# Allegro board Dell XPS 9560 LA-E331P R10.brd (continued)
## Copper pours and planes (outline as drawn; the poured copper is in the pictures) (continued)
LX_1.8V on TOP (solid shape): 247.91,105.29 247.91,103.26 247.71,103.07 245.87,103.07 245.37,103.58 245.37,104.72 246.13,105.48 247.71,105.48
LX_1.8V on BOTTOM (solid shape): 246.31,105.39 246.31,104.72 246.55,104.48 246.86,104.48 247.14,104.76 247.14,105.26 247.24,105.35 248,105.35 248.1,105.25 248.1,103.96 247.78,103.64 247.02,103.64 246.51,103.13 245.81,103.13 245.43,103.51 245.43,103.89 245.43,103.98 246.05,104.6 246.05,104.71 246.05,104.71 246.05,105.4 246.11,105.47 246.23,105.47
LX_1V on BOTTOM (solid shape): 127.76,9.09 127.76,7.82 128.52,7.06 130.49,7.06 130.88,6.67 132.07,6.67 132.07,5.47 130.99,5.47 130.84,5.32 130.84,4.35 129.92,3.44 129.92,2.23 129.67,1.98 127.45,1.98 127.16,2.26 127.16,6.14 126.15,7.14 126.15,9.18 126.31,9.34 127.51,9.34
LX_1VSP on TOP (solid shape): 234.38,115.71 234.38,114.31 234,113.93 232.09,113.93 231.84,114.18 231.84,115.77 231.97,115.9 234.19,115.9
LX_1VSP on TOP (solid shape): 239.84,116.02 239.84,115.2 238.91,114.27 238.87,114.26 238.82,114.25 237.87,114.25 237.75,114.37 237.75,114.82 239.05,116.12 239.75,116.12
LX_1VSP on BOTTOM (solid shape): 238.25,115.45 239.59,115.45 239.71,115.32 239.71,114.44 239.65,114.37 238.44,114.37 238,113.93 238,113.29 237.43,112.72 234.32,112.72 233.87,113.17 233.87,116.02 234.13,116.28 234.32,116.28 234.38,116.34 237.36,116.34
LX_3V on TOP (solid shape): 344.62,23.63 344.62,22.74 344.49,22.61 344.49,21.66 344.3,21.66 344.3,22.55 344.04,22.81 344.04,23.5 344.12,23.58 344.12,23.67 344.21,23.76 344.49,23.76
LX_3V on TOP (solid shape): 339.31,31.62 339.31,25.54 340.24,24.62 340.24,23.63 340.08,23.47 338.17,23.47 336.93,22.23 336.93,19 336.74,18.8 334.27,18.8 333.95,19.12 333.95,20.52 333.63,20.84 331.03,20.84 330.9,20.96 330.9,22.17 331.22,22.49 333.5,22.49 334.33,23.31 334.33,27.5 334.65,27.82 336.49,27.82 336.86,28.2 336.86,30.07 336.68,30.25 336.68,31.98 336.75,32.04 338.89,32.04
LX_3V on IN6 (solid shape): 339.6,28.67 339.6,27.26 341.45,25.41 343.07,25.41 344.73,23.76 344.73,22.74 344.46,22.48 343.72,22.48 342.38,23.81 340.25,23.81 337.82,26.24 337.82,28.67 338.16,29.01 339.26,29.01
LX_5V on TOP (solid shape): 344.49,19.19 344.49,18.3 345.06,17.73 346.77,17.73 347.28,17.22 347.28,16.71 347.16,16.58 345.12,16.58 344.74,16.96 344.74,17.66 344.62,17.79 344.43,17.79 344.3,17.92 344.3,19.19 344.36,19.25 344.43,19.25
LX_5V on TOP (solid shape): 337.69,14.3 337.69,12.14 338.14,11.69 340.11,11.69 340.42,11.38 340.42,10.17 340.11,9.85 338.33,9.85 338.01,9.53 338.01,4.01 337.82,3.82 333.19,3.82 332.87,4.14 332.87,7.82 332.3,8.39 327.47,8.39 326.58,9.28 326.58,11.21 330.23,11.21 330.23,10.08 330.5,9.82 331.68,9.82 331.95,10.08 331.95,11.21 331.75,11.41 330.43,11.41 330.23,11.21 326.58,11.21 326.58,11.38 326.96,11.76 331.03,11.76 332.3,13.03 332.3,14.11 332.74,14.55 337.44,14.55
LX_5V on IN1 (solid shape): 338.77,8.71 338.27,8.2 337.88,8.2 337.38,8.71 336.68,8.71 336.36,9.03 336.36,9.47 336.55,9.66 337.82,9.66
LX_5V on IN1 (solid shape): 348.81,16.9 348.81,16.33 348.5,16.02 348.37,16.02 348.27,15.92 347.45,16.74 346.93,16.74 346.4,17.27 346.4,17.59 346.57,17.76 346.58,17.76 346.74,17.92 347.79,17.92
Net_853 on BOTTOM (solid shape): 241.69,29.93 226.69,29.93 226.69,39.93 241.69,39.93
Net_854 on BOTTOM (solid shape): 210.38,30.43 202.38,30.43 202.38,38.43 210.38,38.43
Net_854 on BOTTOM (solid shape): 222.19,30.3 214.19,30.3 214.19,38.3 222.19,38.3
PBAT_PRES# on TOP (solid shape): 28.87,12.86 28.87,10.47 28.63,10.23 27,10.23 26.58,10.65 26.58,13.44 26.32,13.69 25.4,13.69 25.22,13.88 25.22,14.87 25.35,14.99 26.74,14.99
PP_HV on TOP (solid shape): 25.01,56.13 25.01,55.18 24.66,54.83 23.76,54.83 23.64,54.95 23.64,56 23.54,56.1 23.54,56.97 23.58,57.01 24.12,57.01
PP_HV on BOTTOM (solid shape): 24.05,56.98 24.05,56.79 24.2,56.64 24.36,56.64 24.58,56.42 24.58,56.19 24.58,55.3 24.38,55.1 24.38,54.43 24.07,54.11 24.07,53.45 23.92,53.3 22.97,53.3 22.92,53.35 22.92,54.24 23.59,54.91 23.59,56.01 23.29,56.31 23.29,56.53 23.46,56.7 23.53,56.7 23.7,56.88 23.7,56.95 23.78,57.03 24,57.03
PSID on BOTTOM (solid shape): 19.77,79.22 19.77,72.18 19.63,72.04 19.63,71.99 19.6,71.87 19.6,71.75 19.44,71.58 19.17,71.58 18.92,71.83 18.92,79.22 18.96,79.26 19.74,79.26
RING2 on TOP (solid shape): 12.3,58.78 12.33,58.74 12.37,58.7 12.38,58.68 12.38,58.37 12.61,58.14 13.44,58.14 13.61,57.97 13.61,57.18 13.56,57.13 12.05,57.13 11.74,57.45 11.74,58.63 11.89,58.78
RING2 on BOTTOM (solid shape): 8.9,44.45 8.9,43.37 8.98,43.28 8.98,41.5 8.88,41.41 8.77,41.41 8.71,41.46 8.71,42.5 8.67,42.54 8.67,43.19 8.65,43.2 8.65,43.23 8.42,43.46 8.42,43.88 8.37,43.93 8.37,44.41 8.51,44.55 8.8,44.55
RING2 on IN1 (solid shape): 14.49,57.6 14.49,56.9 14.28,56.69 13.49,56.69 12.99,57.18 12.13,57.18 11.76,57.55 11.76,58.09 11.96,58.29 13.81,58.29
RING2 on IN1 (solid shape): 9.31,45.82 9.31,44.78 9.05,44.52 9.02,44.49 8.99,44.46 8.92,44.24 8.99,44.02 8.99,43.88 8.92,43.69 8.96,43.49 8.76,43.3 8.37,43.3 8.19,43.48 8.19,43.94 8.23,44.1 8.19,44.27 8.13,44.36 8.04,44.42 7.91,44.55 7.91,45.32 7.92,45.33 7.92,45.53 8.29,45.91 9.22,45.91
RING2_L on TOP (solid shape): 11.56,58.88 11.56,58.2 11.11,57.75 7.19,57.75 6.91,57.46 5.71,57.46 5.06,58.11 4.38,58.11 4.35,58.08 4.35,57.92 4.63,57.64 4.63,56.74 3.75,55.86 2.5,55.86 2.35,56.02 2.35,56.68 2.55,56.88 2.94,56.88 3.63,57.57 3.63,58.57 3.73,58.67 4.35,58.67 4.35,58.67 4.48,58.81 4.5,58.82 5.46,58.82 5.77,58.52 5.77,58.51 5.99,58.29 6.31,58.29 6.34,58.33 6.35,58.33 6.96,58.94 11.5,58.94
SD_REG2 on BOTTOM (solid shape): 343.69,39.9 343.69,39.43 343.39,39.13 342.81,39.13 342.81,39.12 341.85,39.12 341.42,38.69 341.34,38.69 341.28,38.75 341.28,39.54 341.62,39.88 342.84,39.88 342.98,40.01 343.57,40.01
SLEEVE on TOP (solid shape): 15.11,57.76 15.11,56.46 15.11,56.46 15.11,56.24 14.88,56.01 14.41,56.01 14.3,56.11 14.3,56.38 13.75,56.93 13.75,57.89 13.85,57.98 14.89,57.98
SLEEVE on TOP (solid shape): 9.53,45.18 9.53,43.59 9.41,43.48 9.12,43.48 9.01,43.59 9.01,44.44 8.86,44.58 8.75,44.58 8.74,44.59 8.64,44.6 8.54,44.59 8.53,44.58 6.87,44.58 6.74,44.71 6.74,45.32 6.83,45.4 9.31,45.4
SLEEVE on BOTTOM (solid shape): 9.54,44.32 9.54,44.06 9.54,44.06 9.54,43.66 9.55,43.65 9.55,43.49 9.36,43.3 9.36,41.49 9.28,41.42 9.18,41.42 9.12,41.48 9.12,43.32 9.02,43.42 9.02,44.3 9.1,44.38 9.48,44.38
SLEEVE on IN2 (solid shape): 15.1,57.09 15.1,55.36 14.99,55.25 14.19,55.25 13.98,55.45 13.98,57.02 14.16,57.2 14.99,57.2
SLEEVE on IN2 (solid shape): 10.19,45.6 10.19,44.64 10.13,44.58 10,44.58 9.92,44.59 9.84,44.58 9.77,44.58 9.71,44.52 9.56,44.23 9.71,43.94 9.71,43.68 9.41,43.38 9.04,43.38 8.94,43.47 8.96,43.51 8.99,43.69 8.93,43.87 8.92,43.88 8.92,43.98 8.94,44 8.94,44.05 8.95,44.06 8.96,44.39 8.7,44.59 8.66,44.6 8.66,45.49 8.9,45.74 10.05,45.74
SLEEVE_L on TOP (solid shape): 3.71,45.77 3.71,45.57 4.02,45.27 4.73,45.27 5.16,45.69 6.29,45.69 6.41,45.57 6.41,44.76 6.35,44.7 3.07,44.7 2.66,45.11 2.66,45.72 2.74,45.8 3.68,45.8
SNB_0.95V on BOTTOM (solid shape): 112.14,58.62 112.14,57.03 112.02,56.9 111,56.9 110.81,57.1 110.81,57.86 110.55,58.11 109.54,58.11 109.48,58.17 109.48,58.68 109.6,58.81 111.95,58.81
SNB_1V on BOTTOM (solid shape): 130.94,9.19 130.94,8.39 130.87,8.32 130.22,8.32 130.03,8.14 130.03,7.58 129.83,7.37 128.84,7.37 128.72,7.5 128.72,9.09 128.91,9.28 130.84,9.28
SNB_1VSP on TOP (solid shape): 235.97,115.83 235.97,115.39 236.22,115.13 237.36,115.13 237.49,115.01 237.49,114.18 237.36,114.05 234.95,114.05 234.76,114.25 234.76,115.9 234.82,115.96 235.84,115.96
SNUB_1.2V on BOTTOM (solid shape): 267.46,27.76 267.46,26.11 267.27,25.92 266.32,25.92 266.19,26.04 266.19,26.74 265.94,27 265.05,27 264.86,27.19 264.86,27.76 265.05,27.95 267.27,27.95
SNUB_3V on TOP (solid shape): 335.18,31.88 335.18,29.95 334.96,29.73 332.78,29.73 332.67,29.83 332.67,30.48 332.81,30.62 333.66,30.62 334.03,30.99 334.03,31.99 334.07,32.03 335.04,32.03
SNUB_5V on TOP (solid shape): 340.3,14.74 340.3,12.9 340.17,12.77 338.46,12.77 338.27,12.96 338.27,14.87 338.46,15.06 339.98,15.06
SW_1.2V on BOTTOM (solid shape): 287.29,28.88 287.29,28.79 287.15,28.65 286.77,28.65 284.93,26.81 284.29,26.81 284.16,26.93 284.16,27.82 284.23,27.89 285.18,27.89 286.24,28.95 287.22,28.95
SW_1.2V on BOTTOM (solid shape): 269.8,33.51 269.8,32.85 270.22,32.43 271.37,32.43 271.53,32.27 271.53,30.3 271.78,30.04 272.37,30.04 272.95,29.47 272.95,25.87 272.86,25.79 268.86,25.79 268.54,26.11 268.54,27.82 266.96,29.41 266.96,33.44 267.14,33.63 269.68,33.63
SW_1.2V on IN6 (solid shape): 272.86,29.39 272.86,28 272.6,27.73 270.82,27.73 270.61,27.94 270.61,29.74 270.75,29.88 272.37,29.88
SW_1.2V on IN6 (solid shape): 286.45,28.45 286.45,28.11 285.59,27.25 283.5,27.25 283.4,27.36 283.4,28.22 283.54,28.36 284.56,28.36 284.77,28.16 285.46,28.16 285.93,28.63 286.28,28.63
SW_+1.35VRUN on TOP (solid shape): 198.31,117.29 198.31,116.59 198.44,116.47 199.91,116.47 200.2,116.18 200.2,111.76 199.98,111.54 199.01,111.54 198.9,111.64 198.9,113.47 198.69,113.67 197.74,113.67 197.55,113.86 197.55,114.44 197.36,114.63 197.36,117.29 197.49,117.42 198.18,117.42
SW_+1.35VRUN on BOTTOM (solid shape): 200.79,117.93 200.79,111.58 200.34,111.13 196.49,111.13 196.15,111.36 195.82,111.13 194.95,111.13 194.69,111.39 194.69,113.99 194.77,114.07 196.41,114.07 196.59,114.25 196.77,114.39 196.79,114.61 196.79,117.29 197.55,118.06 200.66,118.06
TBT_SVR_IND on BOTTOM (solid shape): 24.25,49.89 24.01,49.65 24.01,47.65 23.35,46.99 23.35,46.82 23.34,46.81 23.32,46.69 23.34,46.58 23.35,46.56 23.35,46.08 23.44,46 23.44,45.57 23.37,45.51 23.24,45.51 23.11,45.37 23.11,45.22 23.03,45.14 22.82,45.14 22.72,45.25 22.72,46.28 22.86,46.42 22.86,46.53 22.86,47.33 22.44,47.75 22.44,50.25 22.51,50.45 22.45,50.65 22.44,50.66 22.44,50.77 22.76,51.09 24.25,51.09
TBTA_VBUS_L on BOTTOM (solid shape): 28.54,62.97 28.54,61.85 28.88,61.51 28.88,60.6 28.76,60.47 28.11,60.47 27.76,60.13 27.34,60.13 27.13,60.16 26.96,60.03 26.87,59.94 26.73,59.94 26.7,59.91 26.35,59.91 26.25,59.82 25.68,59.82 25.61,59.84 25.58,59.9 25.51,60.05 25.36,60.11 25.29,60.11 25.2,60.19 25.2,60.48 25.2,60.53 25.34,60.66 25.42,60.66 25.43,60.67 25.47,60.67 25.6,60.8 25.6,60.9 25.61,60.9 25.61,61.07 25.7,61.16 26.32,61.16 26.42,61.26 26.44,61.26 26.68,61.46 26.62,61.77 26.62,62.05 26.63,62.06 26.66,62.2 26.63,62.34 26.63,62.35 26.63,62.77 26.99,63.13 28.39,63.13
TPM_VDD on TOP (solid shape): 158.87,11.98 158.87,11.85 158.86,11.85 158.86,11.23 158.52,10.89 158.52,8.91 158.37,8.76 156.31,8.76 156.25,8.82 156.25,9.02 156.33,9.1 157.5,9.1 157.63,9.23 157.63,9.76 157.4,9.99 157.4,11.99 157.5,12.09 158.76,12.09
UG_3V on TOP (solid shape): 330.69,22.61 330.69,20.92 330.6,20.84 330.07,20.84 329.88,21.03 329.88,22.61 330.01,22.74 330.55,22.74
UG_3V on TOP (solid shape): 343.7,22.26 343.7,21.33 343.66,21.29 343.55,21.29 343.45,21.39 343.45,22.01 343.35,22.11 343.09,22.11 342.46,22.74 342.46,22.93 342.58,23.06 342.9,23.06
UG_3V on IN1 (solid shape): 331.92,22.55 331.92,21.6 331.79,21.47 329.88,21.47 329.82,21.54 329.82,22.74 330.01,22.93 331.53,22.93
UG_3V on IN1 (solid shape): 343.47,23.25 343.47,22.23 343.35,22.11 342.77,22.11 341.76,23.12 341.76,23.44 342.33,24.01 342.71,24.01
UG_5V on TOP (solid shape): 331.82,11.15 331.82,10.14 331.63,9.95 330.55,9.95 330.36,10.14 330.36,11.15 330.49,11.28 331.69,11.28
UG_5V on TOP (solid shape): 343.71,19.28 343.71,18.37 343.63,18.3 342.33,18.3 342.27,18.36 342.27,18.68 342.46,18.87 343.41,18.87 343.47,18.93 343.47,19 343.47,19 343.47,19.25 343.53,19.31 343.68,19.31
UG_5V on IN1 (solid shape): 333.63,11.18 333.44,10.99 333.19,10.99 332.11,9.91 331.66,9.91 331.47,10.11 331.47,11.25 332.11,11.88 333.63,11.88
UG_5V on IN1 (solid shape): 344.3,17.92 344.3,17.15 343.98,16.84 343.73,16.84 342.71,17.85 342.52,17.85 342.2,18.17 342.2,18.61 342.39,18.8 343.41,18.8
VCORE_B+ on TOP (solid shape): 143.32,106.82 143.32,105.86 142.88,105.42 142.11,105.42 141.86,105.67 141.65,105.67 141.54,105.78 141.25,106.07 141.25,106.95 141.33,107.03 143.11,107.03
VCORE_B+ on TOP (solid shape): 140.14,113.42 140.14,112.44 140.91,111.68 140.91,108.25 140.69,108.03 139.11,108.03 138.78,108.36 138.78,113.08 138.84,113.2 138.84,113.32 139.05,113.53 140.03,113.53
VCORE_B+ on TOP (solid shape): 140.21,119.95 140.21,116.28 140.4,116.09 140.8,116.09 140.97,115.92 140.97,114.5 140.72,114.25 139.37,114.25 138.79,114.83 138.79,117.08 138.58,117.28 138.42,117.28 138.37,117.28 137.72,117.28 137.35,117.65 137.35,119.89 137.77,120.31 139.85,120.31
VCORE_B+ on TOP (solid shape): 162.4,118.39 162.4,117.94 162.18,117.72 162.18,117.17 161.99,116.98 161.23,116.98 160.97,116.72 159.8,116.72 159.15,116.08 159.15,115.62 159,115.46 156.08,115.46 155.95,115.59 155.95,117.42 156.18,117.65 156.84,117.65 157.24,118.06 158.34,118.06 158.35,118 158.36,117.95 158.38,117.9 158.41,117.85 158.44,117.81 158.48,117.78 158.52,117.75 158.57,117.72 158.62,117.71 158.67,117.7 158.73,117.7 158.78,117.71 158.83,117.72 158.88,117.75 158.92,117.78 158.96,117.81 159,117.85 159.02,117.9 159.04,117.95 159.05,118 159.06,118.06 159.05,118.11 159.04,118.16 159.02,118.21 159,118.26 158.96,118.3 158.92,118.33 158.88,118.36 158.83,118.39 158.78,118.4 158.73,118.41 158.67,118.41 158.62,118.4 158.57,118.39 158.52,118.36 158.48,118.33 158.44,118.3 158.41,118.26 158.38,118.21 158.36,118.16 158.35,118.11 158.34,118.06 157.24,118.06 157.88,118.69 162.09,118.69
VCORE_B+ on BOTTOM (solid shape): 162.43,118.25 162.43,117.99 162.13,117.69 162.13,117.11 162,116.98 161.48,116.98 161.27,116.76 161.26,116.76 160.64,116.13 159.62,116.13 159.04,115.55 159.04,115.41 159.02,115.39 156.09,115.39 156.02,115.46 156.02,115.83 155.93,115.92 155.39,115.92 155.3,116.01 155.3,116.12 155.32,116.15 155.89,116.15 156.03,116.28 156.03,116.91 156.06,116.94 158.62,116.94 159.26,117.57 159.26,118.09 159.51,118.35 159.59,118.35 159.59,118.39 162.29,118.39
VCORE_B+ on BOTTOM (solid shape): outline of 151 points within 126.48,103.86 143.43,119.39
VCORE_B+ on IN4 (solid shape): outline of 2312 points within 136.91,105.47 162.37,119.64
VCORE_B+ on IN6 (solid shape): 162.43,118.18 162.43,117.85 161.8,117.22 161.64,117.22 160.68,116.26 159.91,116.26 159.13,115.48 156.19,115.48 155.98,115.68 155.98,116.9 156.19,117.1 158.35,117.1 159.19,117.95 159.19,118.14 159.45,118.39 162.22,118.39
VCORE_B+ on IN6 (solid shape): 140.18,119.08 140.18,117.97 140.91,117.24 140.91,114.37 140.82,114.28 140.44,114.28 140.36,114.21 140.36,113.37 140.3,113.17 140.36,112.96 140.36,112.86 140.46,112.76 140.46,112.68 140.21,112.43 140.21,111.44 140.84,110.8 140.84,108.71 140.65,108.53 139.59,108.53 139.32,108.79 139.32,110.58 138.91,110.98 138.91,112.12 139.94,113.15 139.94,113.31 140.08,113.45 140.08,114.21 139.98,114.31 139.57,114.31 139.4,114.49 139.4,116.37 139.45,116.42 139.45,116.62 138.71,117.36 138.23,117.36 137.54,118.04 137.54,119.11 137.8,119.36 139.9,119.36
N09395 on BOTTOM (solid shape): 15.43,39.73 15.43,39.23 15.32,39.12 14.02,39.12 13.72,38.82 13.34,38.82 13.25,38.9 13.25,39.1 12.73,39.63 11.79,39.63 11.75,39.66 11.75,39.8 11.78,39.83 15.32,39.83
N09461 on TOP (solid shape): 13.52,38.07 13.52,37.55 13.45,37.47 13.02,37.47 12.89,37.35 12.89,36.79 12.65,36.55 12.65,36.18 12.55,36.08 12.09,36.08 12.09,36.66 12.39,36.97 12.39,37.64 12.46,37.71 12.46,38.18 12.53,38.25 13.34,38.25
N09461 on BOTTOM (solid shape): 13.66,37.99 13.66,37.57 13.54,37.44 13.17,37.44 12.99,37.63 11.76,37.63 11.71,37.67 11.71,37.78 11.76,37.83 12.74,37.83 12.99,38.07 13.58,38.07
N13272521 on TOP (solid shape): 108.84,61.48 108.84,60.46 108.65,60.27 106.81,60.27 106.68,60.4 106.68,61.03 106.74,61.1 107.63,61.1 108.08,61.54 108.78,61.54
N17034092 on TOP (solid shape): 341.2,22.23 341.2,21.57 341.22,21.57 341.65,21.14 342.04,21.14 342.34,20.84 343.35,20.84 343.41,20.78 343.41,20.64 343.37,20.6 342.31,20.6 342.21,20.7 342.07,20.7 342.07,20.7 341.12,20.7 341.08,20.66 340.35,20.66 340.3,20.7 340.3,22.26 340.39,22.35 341.08,22.35
N19473637 on TOP (solid shape): 182.31,17.43 182.31,16.89 184.09,15.11 184.09,14.19 183.82,13.93 182.65,13.93 182.13,13.41 180.95,13.41 180.87,13.48 180.87,14.55 180.46,14.97 180.46,16.42 180.82,16.79 180.82,17.76 180.89,17.83 181.92,17.83
N19912586 on TOP (solid shape): 177.61,107.13 177.61,104.72 177.27,104.38 176.57,104.38 176.34,104.61 176.34,107.13 176.47,107.26 177.48,107.26
N19912586 on BOTTOM (solid shape): 178.06,108.78 178.06,104.47 177.86,104.28 173.99,104.28 173.67,104.59 173.67,107.51 173.86,107.7 174.75,107.7 175.32,108.28 175.32,108.72 175.58,108.97 177.86,108.97
N22956922 on TOP (solid shape): outline of 1654 points within 193.5,68.02 202.9,91.45
N22956922 on BOTTOM (solid shape): outline of 528 points within 196.04,67.71 202.25,80.79
N22956922 on IN1 (solid shape): outline of 1947 points within 194.37,68.21 202.5,81.73
N48708347 on BOTTOM (solid shape): 283.53,29.09 283.53,26.87 283.47,26.81 282.77,26.81 282.7,26.87 282.7,29.03 282.83,29.16 283.47,29.16
N49571039 on TOP (solid shape): 134,8.06 134,6.8 133.16,5.95 132.66,5.45 131.34,5.45 131.19,5.6 131.19,6.49 131.97,7.27 132.24,7.27 133.17,8.2 133.86,8.2
N52699143 on TOP (solid shape): 33.47,4.45 33.47,1.6 33.4,1.53 31.75,1.53 31.66,1.63 31.66,4.39 31.78,4.52 33.4,4.52
N80922351 on TOP (solid shape): 249.05,110.94 249.05,109.8 248.79,109.55 246.51,109.55 246.44,109.61 246.44,110.86 246.71,111.13 248.86,111.13
N80922351 on BOTTOM (solid shape): 247.59,110.88 247.65,110.82 248.98,110.82 249.05,110.88 249.05,111.32 249.37,111.32 249.68,111.01 249.68,110.18 249.24,109.74 248.6,109.74 248.1,109.23 248.1,108.21 247.91,108.02 246.85,108.02 246.72,107.9 246.72,107.9 246.41,107.59 246.41,107.58 246.3,107.48 246.3,106.84 246.24,106.78 246.1,106.78 246.05,106.83 246.05,107.87 246.13,107.94 246.18,108.04 246.28,108.13 246.28,108.67 246.38,108.77 246.38,110.88 246.83,111.32 247.59,111.32
N80922387 on BOTTOM (solid shape): 249.46,106.38 249.46,104.38 249.34,104.26 248.72,104.26 248.54,104.45 248.54,106.41 248.65,106.53 249.31,106.53
N110703687 on TOP (solid shape): 175.96,100.91 175.96,99.83 175.26,99.13 175.26,97.86 174.94,97.54 173.8,97.54 173.67,97.67 173.67,99.39 173.93,99.64 174.5,99.64 175.07,100.21 175.07,101.04 175.13,101.1 175.77,101.1
N110833423 on TOP (solid shape): 177.93,99.51 177.93,97.86 176.98,96.91 175.79,96.91 175.58,97.13 175.58,99.26 176.02,99.7 177.74,99.7
N110833423 on BOTTOM (solid shape): 177.55,101.6 177.55,97.74 176.77,96.96 173.91,96.96 173.32,97.54 173.32,98.08 172.91,98.5 172.91,101.8 173.1,101.99 177.16,101.99
N111796536 on TOP (solid shape): 312.6,33.87 312.6,33.22 311.28,31.9 309.88,31.9 309.86,31.92 309.86,32.83 309.89,32.86 310.85,32.86 311.93,33.95 312.51,33.95
N111796622 on TOP (solid shape): 313.18,37.09 313.18,36.33 313.04,36.18 312.79,36.18 312.59,35.99 312.59,35.35 312.54,35.3 311.63,35.3 311.56,35.37 311.56,36.11 311.91,36.46 312.1,36.46 312.17,36.52 312.17,37.28 312.23,37.35 312.93,37.35
N116496514 on TOP (solid shape): 175.26,107.07 175.26,105.67 175.83,105.1 175.83,104.02 175.77,103.96 175.13,103.96 174.94,104.15 174.94,104.91 174.5,105.36 173.86,105.36 173.67,105.55 173.67,107.2 173.86,107.39 174.94,107.39
N119942216 on BOTTOM (solid shape): 27.69,79.19 27.69,77.1 27.12,76.53 26.93,76.53 26.54,76.15 26.54,75.57 26.42,75.45 24.65,75.45 24.33,75.13 24.33,72.31 24.2,72.17 20.62,72.17 20.55,72.18 20.49,72.18 20.46,72.18 20.4,72.24 20.4,79.13 20.53,79.26 27.62,79.26
N119944438 on TOP (solid shape): 53.35,16 53.45,16 53.51,15.95 53.51,15.39 52.16,14.04 51.37,14.04 51.18,13.85 51.18,13.34 51.06,13.22 50.8,13.22 50.67,13.34 50.67,13.98 50.74,14.04 50.74,15.34 50.86,15.47 52.29,15.47 52.64,15.82 52.64,15.95 52.71,16.01 53.34,16.01
N120361841 on TOP (solid shape): 57.77,3.03 58.71,3.03 58.77,2.97 58.77,2.44 58.68,2.35 57.1,2.35 56.97,2.47 56.55,2.47 56.43,2.6 56.43,3.26 56.48,3.31 57.49,3.31
N120533729 on TOP (solid shape): 276.93,9.19 276.93,8.86 276.4,8.86 276.4,8.43 276.93,8.43 276.93,7.94 277.16,7.71 277.7,7.71 277.95,7.46 277.95,6.53 277.86,6.44 275.75,6.44 275.63,6.56 275.63,7.32 275.29,7.65 274.49,7.65 274.19,7.95 274.19,8.88 274.58,9.27 276.84,9.27
N120553378 on TOP (solid shape): 309.37,23.63 309.37,21.03 309.25,20.9 307.4,20.9 307.08,21.23 307.08,21.7 307.61,21.7 307.61,22.13 307.07,22.13 307.07,22.82 306.58,23.31 306.58,24.01 306.71,24.14 308.87,24.14
N120970730 on TOP (solid shape): 150.05,101.74 150.05,100.66 149.42,100.02 147,100.02 146.75,100.28 146.75,101.06 146.97,101.28 147,101.28 147.65,101.93 149.86,101.93
N120971346 on BOTTOM (solid shape): 148.53,118.02 148.53,117.76 148.74,117.55 149.42,117.55 149.48,117.48 149.48,116.53 149.29,116.34 147.45,116.34 147.3,116.49 147.3,118.04 147.42,118.15 148.4,118.15
N120971480 on TOP (solid shape): 161.71,111.74 161.71,110.92 161.63,110.84 161.63,109.51 161.56,109.43 159.95,109.43 159.83,109.55 159.83,110.5 159.96,110.63 160.78,110.63 160.85,110.69 160.85,111.64 161.01,111.81 161.64,111.81
N120977227 on TOP (solid shape): 161.65,108.41 161.65,106.83 160.4,105.58 159.73,105.58 158.62,106.69 158.62,108.09 159.51,108.97 161.08,108.97
N120977227 on BOTTOM (solid shape): 158.57,112.98 158.57,112.65 159.27,111.95 161.11,111.95 161.32,111.74 161.32,106.29 160.91,105.88 160.86,105.88 160.71,105.72 159.36,105.72 158.95,106.14 158.93,106.17 158.93,107.17 158.65,107.45 156.02,107.45 155.7,107.77 155.7,112.47 156.05,112.81 156.05,113.04 156.11,113.1 158.44,113.1
N120977227 on IN6 (solid shape): 158.57,113.05 158.57,112.66 159.26,111.97 161.16,111.97 161.32,111.82 161.32,106.28 160.94,105.9 160.86,105.9 160.61,105.65 159.51,105.65 158.98,106.18 158.98,107.15 158.67,107.45 156.03,107.45 155.73,107.76 155.73,112.51 156.4,113.17 158.44,113.17
N120977691 on BOTTOM (solid shape): 146.56,117.93 146.56,116.44 146.56,116.37 147.24,115.68 149.25,115.68 149.4,115.53 149.4,113.78 149.05,113.42 147.96,113.42 147.73,113.19 147.73,112.82 147.71,112.81 147.71,110.85 147.64,110.78 145.2,110.78 144.97,111.01 144.97,113.93 144.21,114.69 143.31,114.69 143.25,114.75 143.25,116.73 143.36,116.85 144.16,116.85 144.46,117.15 144.46,117.99 144.53,118.06 146.43,118.06
N120977691 on IN6 (solid shape): 146.56,117.86 146.56,116.34 147.17,115.73 149.33,115.73 149.53,115.53 149.53,113.75 149.2,113.42 148.24,113.42 147.88,113.06 147.88,112.38 148.44,111.82 148.44,111.39 148.01,110.96 145.16,110.96 144.96,111.16 144.96,113.72 144.98,113.75 144.98,113.9 144.37,114.51 143.37,114.51 143.2,114.68 143.2,116.59 143.33,116.72 144.1,116.72 144.48,117.1 144.48,117.76 144.43,117.81 144.43,117.89 144.58,118.04 146.38,118.04
N121616264 on TOP (solid shape): 192.27,9.3 192.27,7.2 192.2,7.12 191.54,7.12 191.28,7.38 191.28,9.38 191.33,9.43 192.14,9.43
N121617759 on TOP (solid shape): 239.8,7.34 239.8,6.83 240.89,5.74 240.89,5.2 240.84,5.15 238.69,5.15 238.2,5.63 238.2,7.37 238.25,7.43 239.71,7.43
N121617766 on TOP (solid shape): 244.3,7.39 244.3,5.5 243.96,5.16 242.31,5.16 242.27,5.2 242.27,5.86 242.72,6.32 242.72,7.39 242.8,7.47 244.21,7.47
N121795600 on TOP (solid shape): 148.65,103.89 148.65,102.74 148.43,102.51 148.41,102.51 148.15,102.24 147.52,102.24 146.79,101.51 145.52,101.51 144.93,102.09 144.93,103.8 145.15,104.02 148.53,104.02
N121795600 on BOTTOM (solid shape): 144.75,110.47 148.51,110.47 148.97,110.02 148.97,106.1 148.82,105.95 147.86,105.95 147.73,105.83 147.73,104.57 147.83,104.47 148.65,104.47 148.97,104.15 148.97,101.96 148.6,101.59 146.71,101.59 146.6,101.48 145.75,101.48 144.97,102.26 144.97,107.76 143.74,108.99 143.22,108.99 143.19,109.02 143.19,111.03 143.23,111.07 144.15,111.07
N121795600 on IN6 (solid shape): 149.05,110.14 149.05,106.1 148.87,105.93 148.21,105.93 147.8,105.52 147.8,104.96 148.06,104.71 148.59,104.71 148.95,104.35 148.95,102.07 148.51,101.63 145.8,101.63 145.78,101.65 145.56,101.65 144.86,102.35 144.86,107.1 143.99,107.96 143.26,107.96 143.12,108.1 143.12,110.13 143.18,110.19 144.58,110.19 144.96,110.58 148.62,110.58
N122528028 on TOP (solid shape): 237.99,43.8 238.76,43.8 238.84,43.72 238.84,41.72 238.64,41.53 236.64,41.53 236.43,41.74 236.43,42.69 236.3,42.82 235.71,42.82 235.53,42.99 235.53,43.77 235.72,43.96 237.83,43.96
N122754331 on TOP (solid shape): 131.8,67.27 131.8,66.62 131.74,66.56 130.51,66.56 130.41,66.66 129.49,66.66 129.41,66.73 129.41,67.24 129.53,67.36 131.71,67.36
N122912247 on TOP (solid shape): 181.76,82.18 181.76,81.44 182.54,80.66 182.54,79.49 182.29,79.24 181.35,79.24 181.29,79.29 181.29,80.15 181.28,80.15 181.28,80.28 181.03,80.53 181.03,81.28 180.83,81.48 180.37,81.48 180.1,81.75 180.1,82.15 180.21,82.25 181.69,82.25
N123983992 on TOP (solid shape): 114.12,69.63 114.12,67.59 113.79,67.26 111.34,67.26 110.87,67.73 110.87,68.42 110.87,68.42 110.87,69.73 111.19,70.05 113.7,70.05
N123983992 on BOTTOM (solid shape): 110.3,74.37 113.03,74.37 113.04,74.36 114.24,74.36 114.92,73.68 114.92,71.37 114.53,70.98 113.44,70.98 113.35,70.89 113.35,69.85 113.39,69.81 114.56,69.81 114.91,69.45 114.91,66.96 114.78,66.84 111.74,66.84 110.49,68.08 110.49,71.64 109.67,72.46 109.16,72.46 108.97,72.65 108.97,74.68 109.03,74.75 109.92,74.75
N123983992 on IN3 (solid shape): 110.36,74.38 114.3,74.38 114.99,73.69 114.99,71.33 114.61,70.95 113.56,70.95 113.34,70.72 113.34,69.94 113.49,69.78 114.53,69.78 114.91,69.4 114.91,67.04 114.71,66.84 111.76,66.84 110.52,68.08 110.52,71.71 109.7,72.53 109.16,72.53 109.03,72.65 109.03,74.56 109.21,74.74 110.01,74.74
N123983992 on IN4 (solid shape): 110.36,74.38 114.3,74.38 114.99,73.69 114.99,71.33 114.61,70.95 113.56,70.95 113.34,70.72 113.34,69.94 113.49,69.78 114.53,69.78 114.91,69.4 114.91,67.04 114.71,66.84 111.76,66.84 110.52,68.08 110.52,71.71 109.7,72.53 109.16,72.53 109.03,72.65 109.03,74.56 109.21,74.74 110.01,74.74
N123983992 on IN6 (solid shape): 110.36,74.38 114.3,74.38 114.99,73.69 114.99,71.33 114.61,70.95 113.56,70.95 113.34,70.72 113.34,69.94 113.49,69.78 114.53,69.78 114.91,69.4 114.91,67.04 114.71,66.84 111.76,66.84 110.52,68.08 110.52,71.71 109.7,72.53 109.16,72.53 109.03,72.65 109.03,74.56 109.21,74.74 110.01,74.74
N123984012 on TOP (solid shape): 107.89,97.09 107.89,93.61 107.51,93.23 105.73,93.23 105.54,93.42 105.54,93.42 105.48,93.48 105.48,96.34 106.44,97.3 107.67,97.3
N123984012 on BOTTOM (solid shape): 108.91,98.61 108.91,98.61 108.91,98.49 108.93,98.47 109.64,98.47 109.66,98.49 109.66,98.99 110.11,98.99 110.11,98.47 110.12,98.46 110.92,98.46 110.93,98.46 111.41,97.98 111.41,97.4 111.13,97.12 108.5,97.12 108.14,96.76 108.14,92.2 108.09,92.15 107.56,92.15 107.55,92.17 107.55,92.75 107.43,92.87 106.89,92.87 105.98,93.78 105.6,93.78 105.48,93.89 105.48,94.14 105.48,94.4 104.79,95.1 104.79,95.97 104.98,96.17 106.12,96.17 106.55,96.6 106.55,97.1 106.57,97.11 106.57,97.35 107.68,98.47 108.44,98.47 108.46,98.49 108.46,98.99 108.91,98.99
N123984061 on TOP (solid shape): 113.82,96.77 113.82,95.96 113.36,95.5 112.82,95.5 112.59,95.73 112.59,96.73 112.73,96.87 113.72,96.87
N123984061 on BOTTOM (solid shape): 113.3,96.64 113.3,95.94 113.4,95.84 113.86,95.84 113.98,95.72 113.98,95.45 113.84,95.31 112.93,95.31 112.86,95.34 112.79,95.35 112.6,95.54 112.6,96.64 112.73,96.77 113.17,96.77
N123984061 on BOTTOM (solid shape): 109.46,94.71 109.46,91.39 110.65,90.2 110.65,89.21 110.6,89.16 108.59,89.16 108.52,89.1 108.52,88.46 108.52,88.41 108.56,88.38 110.62,88.38 110.65,88.35 110.65,87.17 109.97,86.5 104.78,86.5 104.63,86.65 104.63,88 104.63,88 104.63,88.3 104.73,88.4 106.8,88.4 107.06,88.66 107.06,90.43 107.7,91.07 107.71,91.07 108.4,91.76 108.4,94.32 108.41,94.32 108.41,94.71 108.44,94.75 109.43,94.75
N123984061 on IN6 (solid shape): 113.54,96.66 113.54,95.77 113.35,95.58 112.79,95.58 112.59,95.78 112.59,96.07 112.31,96.35 112.31,96.9 112.58,97.17 113.02,97.17
N123984061 on IN6 (solid shape): 109.48,92.15 109.48,90.94 109.35,90.81 108.21,90.81 108.14,90.88 108.14,91.64 108.52,92.02 108.52,92.21 108.65,92.34 109.28,92.34
N123984063 on BOTTOM (solid shape): 107.38,92.56 107.38,91.13 107.32,91.07 106.43,91.07 106.3,91.19 106.3,92.09 106.89,92.68 107.26,92.68
N123984063 on BOTTOM (solid shape): 117.41,95.89 117.41,95.26 117.39,95.23 117.32,95.22 117.26,95.2 116.81,95.2 116.8,95.2 116.37,95.2 116.27,95.31 115.38,95.31 115.3,95.39 115.3,95.75 115.51,95.96 117.35,95.96
N123984063 on IN6 (solid shape): 107.51,91.58 107.51,90.05 107.5,90.05 107.5,89.87 107.25,89.62 107.06,89.62 107.06,89.67 106.36,90.37 106.36,91.64 106.43,91.7 107.38,91.7
N123984063 on IN6 (solid shape): 117.41,95.89 117.41,95.26 117.35,95.2 116.4,95.2 116.21,95 116.21,94.24 116.02,94.05 115.7,94.05 115.41,94.34 115.41,95.61 115.83,96.02 117.29,96.02
N123984161 on BOTTOM (solid shape): 106.16,91.82 106.16,91.07 106.49,90.74 106.49,89.92 106.36,89.79 104.75,89.79 104.65,89.89 104.65,91.39 104.65,91.39 104.65,91.69 104.87,91.91 106.07,91.91
N123984351 on BOTTOM (solid shape): 113.98,94.03 113.98,93.8 111.76,91.58 109.79,91.58 109.62,91.75 109.62,92.23 109.63,92.23 109.63,92.63 109.7,92.71 110.1,92.71 110.34,92.47 111.51,92.47 113.15,94.1 113.91,94.1
N123984423 on TOP (solid shape): 112.97,73.54 112.97,71.7 112.65,71.38 111.32,71.38 111.06,71.64 111.06,73.61 111.32,73.86 112.65,73.86
N123984459 on TOP (solid shape): 112.59,79.13 112.59,77.22 112.33,76.97 111.09,76.97 110.62,77.45 110.62,79.13 110.75,79.26 112.46,79.26
N123984461 on TOP (solid shape): 115.55,81.8 115.55,80.32 115.11,79.89 110.86,79.89 110.59,80.16 110.59,81.97 111.95,83.32 114.02,83.32
N123984461 on BOTTOM (solid shape): 115.83,84.01 115.83,83.32 115.65,83.14 114.38,83.14 114.25,83.02 114.25,82.15 114.51,81.9 115.65,81.9 115.83,81.72 115.83,79.82 115.65,79.64 110.94,79.64 110.57,80 109.98,80 109.73,80.25 109.73,82.37 109.92,82.56 110.57,82.56 111.06,83.05 111.06,83.83 111.32,84.08 112.52,84.08 113.01,84.57 115.27,84.57
N123984461 on IN3 (solid shape): 115.83,84.01 115.83,83.32 115.65,83.14 114.38,83.14 114.25,83.02 114.25,82.15 114.51,81.9 115.24,81.9 115.52,81.62 115.52,79.79 115.37,79.64 110.94,79.64 110.57,80 110.11,80 109.79,80.32 109.79,82.37 109.98,82.56 110.57,82.56 111.06,83.05 111.06,83.83 111.32,84.08 112.52,84.08 113.01,84.57 115.27,84.57
N123984461 on IN4 (solid shape): 115.83,84.01 115.83,83.32 115.65,83.14 114.38,83.14 114.25,83.02 114.25,82.15 114.51,81.9 115.24,81.9 115.52,81.62 115.52,79.79 115.37,79.64 110.94,79.64 110.57,80 110.11,80 109.79,80.32 109.79,82.37 109.98,82.56 110.57,82.56 111.06,83.05 111.06,83.83 111.32,84.08 112.52,84.08 113.01,84.57 115.27,84.57
N123984461 on IN6 (solid shape): 115.83,84.01 115.83,83.32 115.65,83.14 114.38,83.14 114.25,83.02 114.25,82.15 114.51,81.9 115.24,81.9 115.52,81.62 115.52,79.79 115.37,79.64 110.94,79.64 110.57,80 110.11,80 109.79,80.32 109.79,82.37 109.98,82.56 110.57,82.56 111.06,83.05 111.06,83.83 111.32,84.08 112.52,84.08 113.01,84.57 115.27,84.57
N124494447 on IN2 (solid shape): 21.45,60.39 21.45,57.07 20.91,56.52 20.64,56.52 20.24,56.13 20.03,56.13 19.87,56.29 19.87,56.46 20.45,57.04 20.52,57.04 20.77,57.28 20.77,59.75 20.72,59.8 20.71,59.81 20.5,60.01 20.21,59.98 20.16,59.95 20.03,60.08 20.03,60.71 20.33,61.02 20.82,61.02
N125814267 on TOP (solid shape): 336.17,101.42 336.17,100.66 335.79,100.28 335.79,99.32 335.66,99.2 334.84,99.2 334.65,99.39 334.65,101.48 334.71,101.55 336.04,101.55
N125857121 on TOP (solid shape): 44.84,29.93 44.84,28.39 44.9,28.33 44.9,27.91 44.59,27.59 44.59,26.79 44.45,26.65 42.95,26.65 42.67,26.93 42.67,27.56 43,27.89 43.41,27.89 43.72,28.2 43.72,29.77 43.91,29.95 44.81,29.95
N127291517 on BOTTOM (solid shape): 342.2,45.98 342.2,44.71 342.08,44.59 341.5,44.59 341.12,44.97 341.12,45.31 340.74,45.7 339.99,45.7 339.92,45.77 339.92,46.38 340,46.47 341.71,46.47
N128723303 on TOP (solid shape): 191.01,102.18 191.01,100.85 190.88,100.72 189.23,100.72 189.04,100.91 189.04,102.24 189.49,102.69 190.5,102.69
N128723303 on BOTTOM (solid shape): 190.69,104.66 190.69,102.56 191.07,102.18 192.03,102.18 192.15,102.05 192.15,98.62 191.96,98.43 191.26,98.43 191.23,98.47 188.56,98.47 188.15,98.88 188.15,103.39 187.87,103.67 187.48,103.67 187.2,103.96 187.2,104.59 187.52,104.91 190.44,104.91
N128723349 on TOP (solid shape): 191.03,104.57 191.03,103.58 191.01,103.57 189.47,103.57 189.23,103.32 188.28,103.32 188.09,103.51 188.09,104.21 188.28,104.4 188.98,104.4 189.17,104.6 191,104.6
N128725563 on BOTTOM (solid shape): 163.74,112.87 163.74,110.67 163.64,110.57 163.08,110.57 163.04,110.61 163.04,111.53 162.85,111.72 162.85,112.89 162.89,112.92 163.7,112.92
N128725569 on BOTTOM (solid shape): 173.41,112.44 173.41,110.17 173.36,110.12 172.72,110.12 172.59,110.24 172.59,112.4 172.71,112.52 173.33,112.52
N128726031 on BOTTOM (solid shape): 168.32,113.28 168.32,113.08 168.27,112.99 168.26,112.89 168.26,112.07 168.78,111.54 168.78,110.35 168.68,110.25 167.25,110.25 167.17,110.33 167.17,111.16 167.24,111.24 167.45,111.24 168.03,111.81 168.03,112.08 168.11,112.16 168.11,113.28 168.16,113.33 168.26,113.33
N128727405 on BOTTOM (solid shape): 184.85,111.64 184.85,111.07 184.79,111.01 182.94,111.01 182.88,111.07 182.88,111.9 182.94,111.96 184.53,111.96
N128727995 on BOTTOM (solid shape): 184.15,116.47 184.15,115.83 184.09,115.77 184.09,115.13 183.9,114.94 183.55,114.94 183.2,115.3 182.08,115.3 182.03,115.35 182.03,115.45 182.11,115.53 182.25,115.53 182.25,115.52 182.94,115.52 182.94,115.52 183.01,115.52 183.39,115.9 183.39,116.47 183.52,116.59 184.02,116.59
N128735809 on TOP (solid shape): 8.56,9.34 8.56,8.49 8.8,8.25 8.8,7.23 8.75,7.19 7.14,7.19 7,7.32 7,8.52 7.11,8.63 7.11,9.24 7.24,9.37 8.54,9.37
N128735813 on TOP (solid shape): 11.49,9.21 11.49,7.37 11.3,7.18 10.24,7.18 10.19,7.24 10.19,8.49 10.32,8.62 10.32,9.27 10.45,9.4 11.3,9.4
N128737185 on BOTTOM (solid shape): 217.77,8.07 218.33,8.07 218.33,8.07 218.7,8.07 218.79,7.98 219.68,7.98 219.94,7.71 219.94,7.34 220.29,6.99 220.29,6.87 220.26,6.84 220.26,5.89 220.28,5.76 220.35,5.65 220.35,5.47 219.47,4.59 217.12,4.59 216.73,4.98 216.73,7.94 216.86,8.07 217.75,8.07
N128783984 on TOP (solid shape): 198.76,112.91 198.76,112.28 198.69,112.21 196.28,112.21 196.09,112.4 196.09,112.85 196.28,113.04 198.63,113.04
N128849465 on BOTTOM (solid shape): 139.24,111.21 139.24,110.72 139.17,110.65 138.1,110.65 138.05,110.71 138.05,111.13 137.85,111.33 137.24,111.33 137.16,111.41 137.16,111.84 137.23,111.91 137.89,111.91 137.98,112 138.45,112
N128855110 on BOTTOM (solid shape): 138.77,116.87 139.11,116.87 139.26,116.72 139.26,116.34 139.19,116.28 138.49,116.28 138.3,116.47 138.3,116.67 137.92,117.05 137.52,117.05 137.39,117.18 137.39,117.64 137.44,117.69 137.95,117.69
N128856156 on BOTTOM (solid shape): 159.51,119.12 159.51,118.63 159.01,118.12 159.01,117.87 158.21,117.07 158.11,117.07 158.03,117.16 158.03,117.79 158.03,117.82 158.8,118.59 158.8,119.1 158.89,119.19 159.45,119.19
N128861659 on BOTTOM (solid shape): 105.72,82.63 105.72,81.99 105.67,81.94 105.03,81.94 104.91,82.06 104.91,82.42 104.65,82.68 104.65,82.69 104.4,82.94 103.87,82.94 103.82,82.99 103.82,83.52 103.87,83.57 104.78,83.57
N128862470 on BOTTOM (solid shape): 104.97,76.51 104.97,74.42 104.88,74.33 104.27,74.33 104.13,74.48 104.13,76.55 104.24,76.67 104.81,76.67
N128955571 on TOP (solid shape): outline of 129 points within 18.04,18.03 22.04,21.98
N128958040 on TOP (solid shape): 195.87,116.31 195.87,113.83 195.71,113.67 194.82,113.67 194.69,113.8 194.69,116.4 194.76,116.47 195.71,116.47
N128958713 on TOP (solid shape): 229.62,116.59 229.62,115.07 229.3,114.75 226.12,114.75 225.81,115.07 225.81,116.59 226,116.79 229.43,116.79
N128958713 on BOTTOM (solid shape): 225.76,117.1 231.59,117.1 232.41,116.28 232.41,113.42 232.09,113.1 226.82,113.1 226,113.93 224.41,113.93 224.06,114.28 224.06,115.26 223.53,115.26 223.53,115.71 224.06,115.71 224.06,116.46 223.53,116.46 223.53,116.91 224.06,116.91 224.06,117.66 224.21,117.8 225.06,117.8
N128958750 on TOP (solid shape): 241.24,116.1 241.24,115.13 240.86,114.75 240.86,113.86 240.67,113.67 239.97,113.67 239.84,113.8 239.84,114.69 240.22,115.07 240.22,116.09 240.31,116.18 241.16,116.18
N130300832 on TOP (solid shape): 208.79,51.47 208.79,49.79 208.73,49.73 207.57,49.73 206.81,50.49 205.65,50.49 205.65,50.53 205.18,50.67 205.31,50.19 205.32,50.19 205.36,50.14 205.36,50.12 205.39,49.95 205.49,49.81 205.49,49.31 205.48,49.3 205.48,48.71 205.49,48.7 205.49,45.67 205.37,45.55 204.33,45.55 204.15,45.73 204.15,49.54 204.41,49.88 204.15,50.22 204.15,51.47 204.54,51.86 208.4,51.86
N130673414 on TOP (solid shape): 192.13,86.54 192.13,86.36 192.3,86.19 193.14,86.19 193.47,85.86 193.47,83.89 193.4,83.82 192.59,83.82 192.23,84.18 192.23,85.36 191.96,85.63 190.83,85.63 190.75,85.71 190.75,86.58 190.92,86.75 191.92,86.75

Small or netless copper shapes (teardrops, artwork), in the pictures only: 130 on TOP, 274 on BOTTOM, 2 on IN1, 1 on IN5, 1 on IN6

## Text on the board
Ref Des/Silkscreen Bottom: H48 | FAN L | FAN R | SUPPORT | DDR4 | DIMM-A | ONLY | DIMM-B
User.Comments: Issued | PROJECT | BOARD NO. | LAYER NO. | DRAW BY | Security level | Decipherment date | COMPAL ELECTRONICS. INC. | Date | LA-C361P | LA-E331P | Confidential | COMP.SIDE | 2016-01-22 | 2015-01-22 | 2017-10-20 | 2016-10-20 | AAM00 | CAM00/01 | Win | Moopi | REV:0.3(X02)
Ref Des/Silkscreen Top: H38 | H37 | SH1
IN5: IN5
IN6: IN6
BODY_CENTER: AGND | GND | +DC_IN | +SDC_IN | +3VALW | +1V_MPHY | +5VS | +VCCGT | +3VS | B+ | +VCC_CORE | +1.2V_DDR | +GPU_CORE | +1.35VSDGPU | +5V_CHGUSB_1
COMPVAL_TYPE_TOP: L7 | L8 | L9 | L10 | L11 | L12 | GND3 | IN5 | IN6 | IN4 | VCC
User.43: Width/space | trace Width | 3.8 / 3.5 | 4.8mil | 3.2 / 3.3 | 90 ohm | 42 ohm | 91 ohm
User.44: FIGURE | SIZE | 8.0 | 16.0 | 20.0 | 26.0 | 30.0 | 33.0 | 36.0 | 91.0 | 98.0 | 110.0 | 126.0 | 154.0 | 165.0 | 35.0 | 40.0 | 43.0 | 63.0 | 83.0 | 236.0 | 43.0x24.0 | 47.0x22.0 | 47.0x24.0 | 63.0x24.0 | 67.0x39.0 | 75.0x24.0 | 37.0x30.0 | 98.0x83.0 | 114.0x83.0 | DRILL CHART: TOP to BOTTOM | ALL UNITS ARE IN MILS | TOLERANCE | +3.0/-3.0 | +2.0/-2.0 | PLATED | NON-PLATED | QTY | 8682 | 12 | 19 | 2 | 18 | 4 | 5 | 1 | 6 | 8
